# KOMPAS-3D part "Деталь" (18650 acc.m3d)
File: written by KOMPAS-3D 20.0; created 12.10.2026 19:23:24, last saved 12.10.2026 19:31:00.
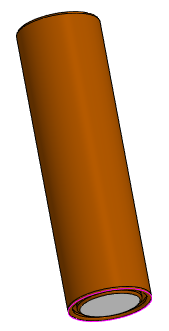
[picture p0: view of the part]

Document properties: Полное имя файла: D:\myProjects\Progect_esp32\box_compas\ups 18650\18650 acc.m3d

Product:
- Part/product: Деталь
    Масса: 0.12809

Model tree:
1. Эскиз:1
2. Элемент выдавливания:1
     Расстояние 1 = 65
3. Эскиз:2  (with: Элемент выдавливания:1)
4. Элемент выдавливания:2
     Расстояние 2 = 1
5. Эскиз:3  (with: Элемент выдавливания:1)
6. Элемент выдавливания:3
     Расстояние 2 = 1
7. Скругление:1  (with: Элемент выдавливания:3, Элемент выдавливания:1, Элемент выдавливания:2)
     Радиус = 0.5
